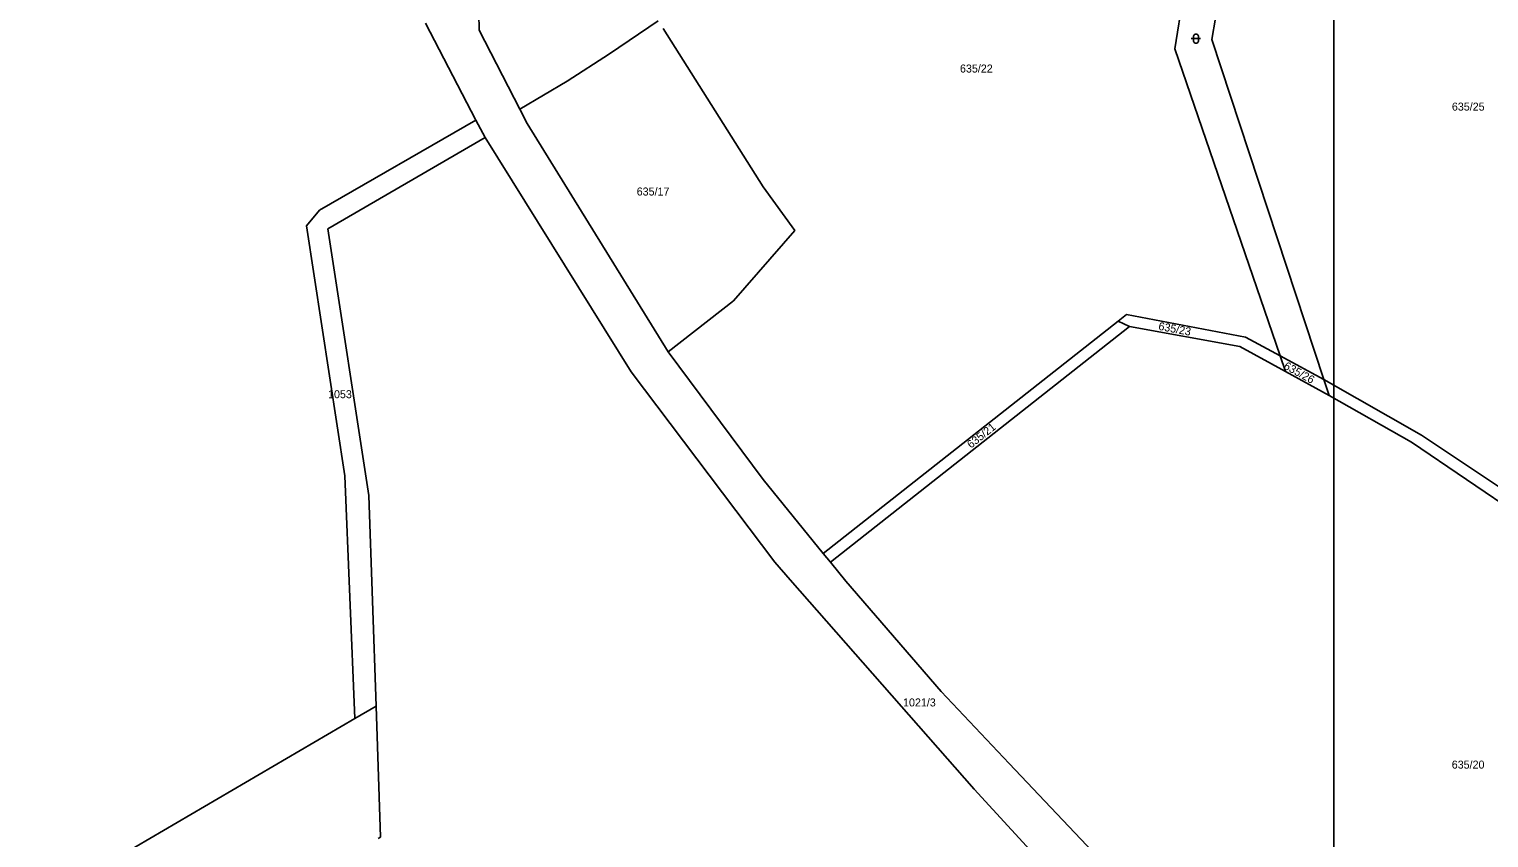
# Model space of a CAD drawing. Extents: x -801907 to -800293, y -1017000 to -1015684.
# Drawn here: x -800902.2 to -800592.1, y -1016304.7 to -1016132.8 of the extents above; entities that cross this region are included whole.
import ezdxf

# ---------------------------------------------------------------- set-up
doc = ezdxf.new("R2010")
doc.units = 0
for name, color, linetype in [('Default', 7, 'Continuous'), ('KLADY_ZMVM', 7, 'Continuous'), ('KN_HRANICE', 7, 'Continuous'), ('KN_KULTURY', 7, 'Continuous'), ('KN_PARCELY', 7, 'Continuous')]:
    doc.layers.add(name, color=color, linetype=linetype)

# ---------------------------------------------------------------- blocks, each defined once
blk = doc.blocks.new('316')
at = {"layer": 'Default'}
for points in [[(-1, 1), (0.27, 1), (1, 1)], [(-0.5, 1.5), (-0.4, 1.79), (-0.15, 1.97), (0.16, 1.97), (0.41, 1.79), (0.51, 1.5), (0.51, 0.5), (0.41, 0.21), (0.16, 0.03), (-0.15, 0.03), (-0.4, 0.21), (-0.5, 0.5), (-0.5, 1.5)]]:
    blk.add_lwpolyline(points, dxfattribs=at)

msp = doc.modelspace()

# ---------------------------------------------------------------- linework, layer by layer
at = {"layer": 'KLADY_ZMVM'}
msp.add_lwpolyline([(-800625, -1016000), (-800625, -1016500), (-800625, -1017000)], dxfattribs=at)
at = {"layer": 'KN_HRANICE'}
for p, q in [((-800649.62, -1016080.7), (-800658.77, -1016137)), ((-800642.01, -1016082.06), (-800650.89, -1016135.02)), ((-800806.9, -1016116.78), (-800806.54, -1016133.07)), ((-800768.52, -1016131.08), (-800778.84, -1016138.06)), ((-800817.98, -1016131.56), (-800807.23, -1016152.14)), ((-800806.54, -1016133.07), (-800797.93, -1016149.82)), ((-800767.44, -1016132.7), (-800746.19, -1016166.34)), ((-800658.77, -1016137), (-800636.42, -1016202.22)), ((-800650.89, -1016135.02), (-800627.11, -1016207.26)), ((-800778.84, -1016138.06), (-800787.87, -1016143.9)), ((-800787.87, -1016143.9), (-800797.93, -1016149.82)), ((-800797.93, -1016149.82), (-800796.36, -1016152.89)), ((-800840.49, -1016171.3), (-800807.23, -1016152.14)), ((-800807.23, -1016152.14), (-800805.29, -1016155.85)), ((-800796.36, -1016152.89), (-800766.37, -1016201.36)), ((-800805.29, -1016155.85), (-800838.71, -1016175.29)), ((-800805.29, -1016155.85), (-800774.29, -1016205.68)), ((-800746.19, -1016166.34), (-800739.51, -1016175.64)), ((-800840.49, -1016171.3), (-800843.21, -1016174.61)), ((-800843.21, -1016174.61), (-800835.06, -1016227.76)), ((-800838.71, -1016175.29), (-800829.97, -1016231.91)), ((-800739.51, -1016175.64), (-800752.56, -1016190.54)), ((-800752.56, -1016190.54), (-800766.37, -1016201.36)), ((-800670.83, -1016194.89), (-800733.45, -1016244.24)), ((-800668.38, -1016196), (-800731.92, -1016246.12)), ((-800669.02, -1016193.47), (-800670.83, -1016194.89)), ((-800670.83, -1016194.89), (-800668.38, -1016196)), ((-800643.75, -1016198.25), (-800669.02, -1016193.47)), ((-800668.38, -1016196), (-800644.93, -1016200.27)), ((-800636.42, -1016202.22), (-800643.75, -1016198.25)), ((-800766.37, -1016201.36), (-800746.21, -1016228.54)), ((-800644.93, -1016200.27), (-800635.27, -1016205.57)), ((-800627.11, -1016207.26), (-800636.42, -1016202.22)), ((-800636.42, -1016202.22), (-800635.27, -1016205.57)), ((-800774.29, -1016205.68), (-800743.77, -1016246.11)), ((-800626, -1016210.64), (-800635.27, -1016205.57)), ((-800606.39, -1016219.1), (-800627.11, -1016207.26)), ((-800627.11, -1016207.26), (-800626, -1016210.64)), ((-800626, -1016210.64), (-800608.51, -1016220.58)), ((-800608.51, -1016220.58), (-800576, -1016242.64)), ((-800577.22, -1016238.6), (-800606.39, -1016219.1)), ((-800835.06, -1016227.76), (-800832.94, -1016279.31)), ((-800746.21, -1016228.54), (-800733.45, -1016244.24)), ((-800829.97, -1016231.91), (-800828.45, -1016276.68)), ((-800733.45, -1016244.24), (-800731.92, -1016246.12)), ((-800743.77, -1016246.11), (-800740.47, -1016249.87)), ((-800731.92, -1016246.12), (-800728.65, -1016250.14)), ((-800740.47, -1016249.87), (-800701.43, -1016294.3)), ((-800728.65, -1016250.14), (-800708.39, -1016273.55)), ((-800708.39, -1016273.55), (-800693.94, -1016288.84)), ((-800832.94, -1016279.31), (-800828.45, -1016276.68)), ((-800828.45, -1016276.68), (-800827.51, -1016304.5)), ((-800902.15, -1016319.78), (-800832.94, -1016279.31)), ((-800693.94, -1016288.84), (-800661.88, -1016322.76)), ((-800701.43, -1016294.3), (-800671.28, -1016327.06)), ((-800827.51, -1016304.5), (-800828.01, -1016304.81))]:
    msp.add_line(p, q, dxfattribs=at)

# ---------------------------------------------------------------- block references
at = {"layer": 'KN_KULTURY'}
msp.add_blockref('316', (-800654.28, -1016135.85), dxfattribs=at)

# ---------------------------------------------------------------- texts
at = {"layer": 'KN_PARCELY'}
for s, p in [('635/22', (-800704.41, -1016142.05)), ('635/25', (-800599.91, -1016150.14)), ('635/17', (-800773.09, -1016168.18)), ('1053', (-800838.66, -1016211.25)), ('1021/3', (-800716.51, -1016276.74)), ('635/20', (-800599.94, -1016289.95))]:
    msp.add_text(s, height=1.7, dxfattribs=at).set_placement(p)
for s, rotation, p in [('635/23', 349.332, (-800662.35, -1016196.7)), ('635/26', 331.17, (-800635.79, -1016204.89)), ('635/21', 38.388, (-800702.08, -1016221.99))]:
    msp.add_text(s, height=1.7, rotation=rotation, dxfattribs=at).set_placement(p)

doc.saveas('drawing.dxf')
